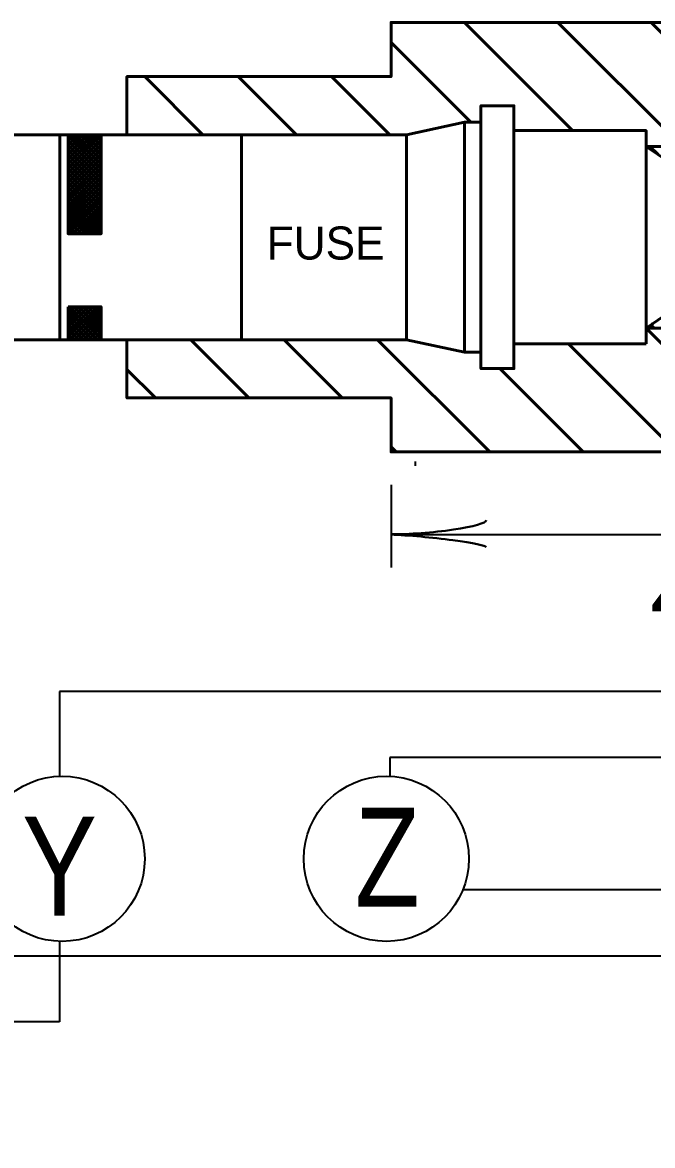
# Model space of a CAD drawing. Extents: x -32 to 824, y -6 to 538.
# Drawn here: x 622.71 to 645.6, y 226.84 to 267.63 of the extents above; entities that cross this region are included whole.
import ezdxf

# ---------------------------------------------------------------- set-up
doc = ezdxf.new("R2010")
doc.units = 0
doc.header["$LTSCALE"] = 1.1
doc.layers.add('1', color=7, linetype='Continuous', lineweight=53)

msp = doc.modelspace()

# ---------------------------------------------------------------- linework, layer by layer
at = {"layer": '1'}
for p, q in [((642.694, 263.707), (638.768, 267.633)), ((646.662, 263.133), (642.162, 267.633)), ((650.056, 263.133), (645.556, 267.633)), ((639, 264.007), (636.106, 266.901)), ((629.268, 263.557), (627.155, 265.67)), ((632.662, 263.557), (630.549, 265.67)), ((636.056, 263.557), (633.943, 265.67)), ((638.769, 264.007), (638.769, 263.707)), ((639.369, 264.007), (639.369, 255.659)), ((624.369, 263.557), (618.669, 263.557)), ((618.669, 263.557), (623.631, 263.557)), ((624.069, 256.109), (624.069, 263.557)), ((624.369, 263.524), (624.403, 263.557)), ((624.369, 263.354), (624.572, 263.557)), ((624.369, 263.184), (624.742, 263.557)), ((624.369, 263.014), (624.912, 263.557)), ((624.369, 262.845), (625.081, 263.557)), ((624.369, 262.675), (625.251, 263.557)), ((624.369, 262.505), (625.421, 263.557)), ((625.569, 262.474), (624.487, 263.557)), ((625.569, 262.644), (624.656, 263.557)), ((625.569, 262.814), (624.826, 263.557)), ((625.569, 262.983), (624.996, 263.557)), ((625.569, 263.153), (625.165, 263.557)), ((625.569, 263.323), (625.335, 263.557)), ((625.569, 263.493), (625.505, 263.557)), ((625.569, 263.557), (626.506, 263.557)), ((636.669, 263.557), (625.766, 263.557)), ((630.669, 256.109), (630.669, 263.557)), ((636.669, 256.109), (636.669, 263.557)), ((638.769, 263.707), (638.769, 255.959)), ((640.569, 263.707), (640.569, 255.959)), ((624.369, 262.336), (625.569, 263.536)), ((625.569, 262.305), (624.369, 263.505)), ((624.369, 262.166), (625.569, 263.366)), ((625.569, 262.135), (624.369, 263.335)), ((624.369, 261.996), (625.569, 263.196)), ((625.569, 261.965), (624.369, 263.165)), ((624.369, 261.827), (625.569, 263.026)), ((625.569, 261.796), (624.369, 262.996)), ((624.369, 261.657), (625.569, 262.857)), ((625.569, 261.626), (624.369, 262.826)), ((648.369, 261.079), (645.369, 263.133)), ((645.405, 263.109), (645.429, 263.133)), ((645.505, 263.04), (645.599, 263.133)), ((645.803, 262.836), (645.506, 263.133)), ((624.369, 261.487), (625.569, 262.687)), ((625.569, 261.456), (624.369, 262.656)), ((624.369, 261.317), (625.569, 262.517)), ((625.569, 261.286), (624.369, 262.487)), ((624.369, 261.148), (625.569, 262.348)), ((625.569, 261.117), (624.369, 262.317)), ((624.369, 260.978), (625.569, 262.178)), ((625.569, 260.947), (624.369, 262.147)), ((624.369, 260.808), (625.569, 262.008)), ((625.569, 260.777), (624.369, 261.977)), ((645.369, 257.459), (645.369, 262.207)), ((624.369, 260.639), (625.569, 261.839)), ((625.569, 260.608), (624.369, 261.808)), ((624.369, 260.469), (625.569, 261.669)), ((625.569, 260.438), (624.369, 261.638)), ((624.369, 260.299), (625.569, 261.499)), ((625.569, 260.268), (624.369, 261.468)), ((624.369, 260.129), (625.569, 261.329)), ((625.569, 260.099), (624.369, 261.298)), ((624.369, 259.96), (625.569, 261.16)), ((625.541, 259.957), (624.369, 261.129)), ((625.371, 259.957), (624.369, 260.959)), ((625.202, 259.957), (624.369, 260.789)), ((624.536, 259.957), (625.569, 260.99)), ((624.706, 259.957), (625.569, 260.82)), ((625.032, 259.957), (624.369, 260.62)), ((624.862, 259.957), (624.369, 260.45)), ((624.692, 259.957), (624.369, 260.28)), ((624.875, 259.957), (625.569, 260.651)), ((625.045, 259.957), (625.569, 260.481)), ((625.215, 259.957), (625.569, 260.311)), ((624.523, 259.957), (624.369, 260.111)), ((625.385, 259.957), (625.569, 260.142)), ((625.554, 259.957), (625.569, 259.972)), ((645.369, 256.533), (648.369, 258.587)), ((645.369, 257.459), (645.369, 255.959)), ((624.369, 257.25), (624.428, 257.309)), ((624.369, 257.08), (624.598, 257.309)), ((624.369, 256.911), (624.768, 257.309)), ((624.369, 256.741), (624.938, 257.309)), ((624.369, 256.571), (625.107, 257.309)), ((624.369, 256.401), (625.277, 257.309)), ((624.369, 256.232), (625.447, 257.309)), ((625.435, 256.109), (624.369, 257.175)), ((625.569, 256.145), (624.404, 257.309)), ((624.416, 256.109), (625.569, 257.262)), ((625.569, 256.314), (624.574, 257.309)), ((624.586, 256.109), (625.569, 257.092)), ((625.569, 256.484), (624.744, 257.309)), ((625.569, 256.654), (624.914, 257.309)), ((625.569, 256.824), (625.083, 257.309)), ((625.569, 256.993), (625.253, 257.309)), ((625.569, 257.163), (625.423, 257.309)), ((625.265, 256.109), (624.369, 257.005)), ((625.095, 256.109), (624.369, 256.836)), ((624.926, 256.109), (624.369, 256.666)), ((624.756, 256.109), (625.569, 256.923)), ((624.926, 256.109), (625.569, 256.753)), ((645.447, 256.533), (645.617, 256.703)), ((645.657, 256.533), (645.54, 256.65)), ((624.756, 256.109), (624.369, 256.496)), ((624.586, 256.109), (624.369, 256.327)), ((625.095, 256.109), (625.569, 256.583)), ((625.265, 256.109), (625.569, 256.413)), ((625.435, 256.109), (625.569, 256.244)), ((649.87, 252.033), (645.37, 256.533)), ((645.488, 256.533), (645.439, 256.581)), ((624.417, 256.109), (624.369, 256.157)), ((625.569, 256.109), (626.506, 256.109)), ((636.669, 256.109), (626.028, 256.109)), ((630.936, 253.996), (628.823, 256.109)), ((634.33, 253.996), (632.217, 256.109)), ((639.687, 252.033), (635.611, 256.109)), ((638.769, 255.959), (638.769, 255.659)), ((646.475, 252.033), (642.549, 255.959)), ((627.542, 253.996), (626.506, 255.032)), ((643.081, 252.033), (640.055, 255.059)), ((636.293, 252.033), (636.106, 252.22))]:
    msp.add_line(p, q, dxfattribs=at)
at = {"layer": '1', "lineweight": 35}
for p, q in [((636.983, 251.689), (636.983, 251.533)), ((636.106, 250.833), (636.106, 247.833)), ((636.106, 249.033), (669.658, 249.033)), ((673.258, 243.333), (624.058, 243.333)), ((624.058, 243.333), (624.058, 240.25)), ((686.458, 240.933), (636.058, 240.933)), ((636.058, 240.933), (636.058, 240.249)), ((638.715, 236.133), (683.839, 236.133)), ((624.058, 234.253), (624.058, 231.333)), ((612.361, 233.733), (673.125, 233.733))]:
    msp.add_line(p, q, dxfattribs=at)
at = {"layer": '1'}
for points in [[(626.506, 263.557), (626.506, 265.67), (636.106, 265.67), (636.106, 267.633), (652.858, 267.633), (652.858, 266.733), (660.058, 264.633), (669.658, 264.633), (669.658, 261.633), (661.258, 261.633), (660.658, 263.133), (645.369, 263.133), (645.369, 263.707), (640.569, 263.707), (640.569, 264.607), (639.369, 264.607), (639.369, 264.007), (638.769, 264.007), (636.669, 263.557)], [(645.369, 257.459), (645.369, 262.207), (645.369, 263.707), (645.369, 263.133)], [(645.369, 263.133), (660.658, 263.133), (661.258, 261.633), (669.658, 261.633), (681.658, 261.633), (681.658, 258.033), (669.658, 258.033), (661.258, 258.033), (660.658, 256.533), (645.369, 256.533)], [(645.369, 262.207), (645.369, 257.459), (645.369, 255.959)], [(626.506, 256.109), (626.506, 253.996), (636.106, 253.996), (636.106, 252.033), (652.858, 252.033), (652.858, 252.933), (660.058, 255.033), (669.658, 255.033), (669.658, 258.033), (661.258, 258.033), (660.658, 256.533), (645.369, 256.533)], [(645.369, 255.959), (645.369, 257.459), (645.369, 255.959)], [(624.369, 256.109), (618.669, 256.109), (623.226, 256.109)], [(645.369, 255.959), (640.569, 255.959), (640.569, 255.059), (639.369, 255.059), (639.369, 255.659), (638.769, 255.659), (636.669, 256.109)]]:
    msp.add_lwpolyline(points, dxfattribs=at)
for points in [[(624.369, 263.557), (625.569, 263.557), (625.569, 259.957), (624.369, 259.957)], [(624.369, 257.309), (625.569, 257.309), (625.569, 256.109), (624.369, 256.109)]]:
    msp.add_lwpolyline(points, close=True, dxfattribs=at)
at = {"layer": '1', "lineweight": 35}
msp.add_lwpolyline([(624.058, 231.333), (616.741, 231.333), (616.741, 226.837)], dxfattribs=at)
for centre in [(624.153, 237.252), (635.932, 237.252)]:
    msp.add_circle(centre, 3, dxfattribs=at)
at = {"layer": '1', "lineweight": 40}
for centre, major_axis, ratio, start_param, end_param in [((637.416, 249.365), (-2.143, -0.187), 0.122415, 0.896353, 3.141593), ((637.451, 248.779), (-2.108, 0.211), 0.07063, 3.140715, 5.41811)]:
    msp.add_ellipse(centre, major_axis=major_axis, ratio=ratio, start_param=start_param, end_param=end_param, dxfattribs=at)

# ---------------------------------------------------------------- texts
at = {"layer": '1'}
msp.add_text('FUSE', height=1.2, dxfattribs=at).set_placement((631.586, 259.021))
for s, height, width, p in [('47.6mm', 2.4, 1.2, (645.508, 245.697)), ('Z', 3.6, 0.8, (634.791, 235.515)), ('Y', 3.6, 0.85, (622.694, 235.186))]:
    msp.add_text(s, height=height, dxfattribs=dict(at, width=width)).set_placement(p)

doc.saveas('drawing.dxf')
